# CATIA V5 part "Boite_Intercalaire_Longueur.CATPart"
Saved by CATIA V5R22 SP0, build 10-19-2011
Part number: Boite_Intercalaire_Longueur
Bounding box of the stored display mesh (mm): x -88 to 88, y -2.5 to 2.5, z -15 to 15
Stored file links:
  U:\S9A\PER\CAO\Assemblage\Reservoir_Boite\Boite\Boite_Intercalaire_Longueur.CATPart
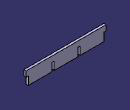
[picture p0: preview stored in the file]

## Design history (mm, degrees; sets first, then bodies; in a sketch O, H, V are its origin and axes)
Body1 (main body)
  Sketch1 on zx-plane, origin (0, 0, 0), H (-1, 0, 0), V (0, 0, 1)
    line L1 (-88, 15) -> (88, 15)
    line L2 (88, 15) -> (88, -15)
    line L3 (88, -15) -> (-88, -15)
    line L4 (-88, -15) -> (-88, 15)
    distance L1 L3 = 30
    distance L2 L4 = 176
    horizontal: L1 H, L3 H
    vertical: L2 V, L4 V
    symmetry: L2 L4 V, L1 L3 H
  Pad1: profile Sketch1, direction (0, 1, 0), length 2.5, mirrored extent
  Sketch2 on zx-plane, origin (0, 0, 0), H (-1, 0, 0), V (0, 0, 1)
    line L1 (83, 3) -> (88, 3)
    line L2 (88, 3) -> (88, -15)
    line L3 (88, -15) -> (83, -15)
    line L4 (83, -15) -> (83, 3)
    reference projected line E1 (-88, -15) -> (88, -15) from edge [face of Pad1 from Sketch1.L3 | end face of Pad1]
    reference projected line E2 (88, -15) -> (88, 15) from edge [face of Pad1 from Sketch1.L2 | end face of Pad1]
    distance L4 L2 = 5
    distance L3 L1 = 18
    horizontal: L1 H, L3 H
    vertical: L2 V, L4 V
    coincidence: L3 E1, E2 L2
  Pocket1: profile Sketch2, direction (0, -1, 0), length 5, mirrored extent
  Mirror1: of Pocket1, about yz-plane
  Sketch3 on zx-plane, origin (0, 0, 0), H (-1, 0, 0), V (0, 0, 1)
    line L1 (-31, 3) -> (-26, 3)
    line L2 (-26, 3) -> (-26, -15)
    line L3 (-26, -15) -> (-31, -15)
    line L4 (-31, -15) -> (-31, 3)
    reference projected line E1 (-88, -15) -> (88, -15) from edge [face of Pad1 from Sketch1.L3 | end face of Pad1]
    distance L2 L4 = 5
    distance L1 L3 = 18
    distance V L2 = 26
    horizontal: L1 H, L3 H
    vertical: L2 V, L4 V
    coincidence: L3 E1
  Pocket2: profile Sketch3, direction (0, -1, 0), length 5, mirrored extent
  Mirror2: of Pocket2, about yz-plane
